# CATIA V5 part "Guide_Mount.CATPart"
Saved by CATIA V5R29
Part number: Guide_Mount_01
Source: Unknown
Bounding box of the stored display mesh (mm): x -50 to 50, y 0 to 132, z -45 to 45
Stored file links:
  C:\가치같이\SmartFactory_BoxErectorConveyor\Guide_Mount.CATPart
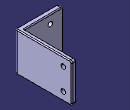
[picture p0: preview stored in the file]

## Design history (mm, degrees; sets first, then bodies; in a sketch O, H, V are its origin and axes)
Body1 (main body)
  Solid1 "PartBody": solid without history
